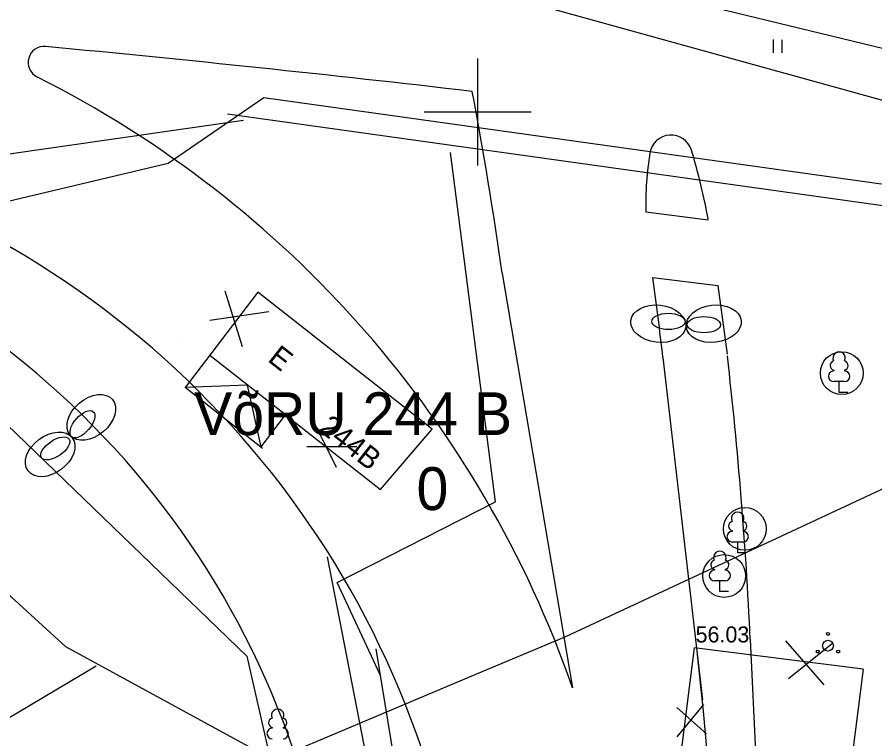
# Model space of a CAD drawing. Extents: x 9156 to 9809, y 2728 to 4000.
# Drawn here: x 9478.48 to 9518.57, y 3670.71 to 3704.43 of the extents above; entities that cross this region are included whole.
import ezdxf

# ---------------------------------------------------------------- set-up
doc = ezdxf.new("R2010")
doc.units = 0
for name, color, linetype in [('Level 12', 7, 'Continuous'), ('Level 15', 7, 'Continuous'), ('Level 17', 7, 'Continuous'), ('Level 18', 7, 'Continuous'), ('Level 21', 7, 'Continuous'), ('Level 5', 7, 'Continuous'), ('Level 54', 7, 'Continuous'), ('Level 56', 7, 'Continuous'), ('Level 7', 7, 'Continuous'), ('Level 8', 7, 'Continuous')]:
    doc.layers.add(name, color=color, linetype=linetype)

msp = doc.modelspace()

# ---------------------------------------------------------------- linework, layer by layer
at = {"layer": 'Level 12'}
for p, q in [((9488.307, 3699.92), (9534.248, 3693.484)), ((9459.613, 3695.388), (9489.062, 3699.618)), ((9500.841, 3681.791), (9498.727, 3698.107)), ((9493.441, 3678.014), (9500.841, 3681.791)), ((9495.459, 3673.67), (9493.441, 3678.014)), ((9498.274, 3656.637), (9495.253, 3674.917))]:
    msp.add_line(p, q, dxfattribs=at)
at = {"layer": 'Level 15'}
msp.add_lwpolyline([(9437.581, 3686.241), (9462.367, 3692.104), (9485.532, 3697.606), (9490, 3700.675), (9527.906, 3695.387)], dxfattribs=at)
at = {"layer": 'Level 17'}
msp.add_line((9496.063, 3663.383), (9492.991, 3679.211), dxfattribs=at)
msp.add_arc((9453.534, 3657.259), 40, 9.3105, 75.7638, dxfattribs=at)
at = {"layer": 'Level 18'}
for p, q in [((9507.867, 3695.337), (9510.78, 3694.968)), ((9501.153, 3692.453), (9504.44, 3673.096)), ((9508.194, 3692.272), (9511.23, 3691.887)), ((9511.23, 3691.887), (9511.666, 3688.685)), ((9508.665, 3688.523), (9510.518, 3672.533)), ((9512.748, 3675.359), (9513.212, 3665.616))]:
    msp.add_line(p, q, dxfattribs=at)
for centre, radius, start, end in [((9479.737, 3702.313), 0.75, 84.5765, 243.2936), ((9386.491, 2720.179), 987.3, 83.412623, 84.576467), ((9456.66, 3656.441), 50.6, 19.2175, 63.2936), ((9312.974, 3665.85), 190.05, 8.05166, 10.6463), ((9509.042, 3697.925), 1, 16.7546, 170.8283), ((9481.608, 3689.666), 29.65, 10.3017, 16.7546), ((9456.66, 3656.441), 43, 11.6855, 74.8696), ((9522.863, 3695.693), 15, 170.8283, 181.3602), ((9312.974, 3665.85), 197, 6.60881, 7.70773), ((9312.974, 3665.85), 200, 2.72499, 6.53209), ((9360.923, 3657.331), 150.35, 345.17244, 6.60878)]:
    msp.add_arc(centre, radius, start, end, dxfattribs=at)
at = {"layer": 'Level 21'}
for p, q in [((9488.177, 3691.646), (9489.001, 3689.036)), ((9487.49, 3690.273), (9490.236, 3690.685)), ((9486.209, 3689.434), (9486.209, 3689.434)), ((9492.296, 3685.601), (9493.394, 3683.403)), ((9492.021, 3684.365), (9494.355, 3684.365)), ((9514.399, 3675.297), (9516.184, 3673.236)), ((9516.596, 3675.16), (9514.536, 3673.511)), ((9510.555, 3672.316), (9509.319, 3670.804)), ((9509.319, 3672.178), (9510.692, 3670.942))]:
    msp.add_line(p, q, dxfattribs=at)
for centre in [(9517.021, 3687.799), (9512.491, 3680.518), (9511.53, 3678.319)]:
    msp.add_circle(centre, 1, dxfattribs=at)
at = {"layer": 'Level 54'}
for p, q in [((9525.323, 3698.769), (9500, 3705.781)), ((9509.597, 3705.253), (9524.201, 3701.7)), ((9513.819, 3703.38), (9513.819, 3702.76)), ((9514.224, 3703.369), (9514.224, 3702.76)), ((9500, 3702.5), (9500, 3697.5)), ((9500, 3702.5), (9500, 3697.5)), ((9500, 3702.5), (9500, 3697.5)), ((9500, 3702.5), (9500, 3697.5)), ((9500, 3702.5), (9500, 3697.5)), ((9500, 3702.5), (9500, 3697.5)), ((9500, 3702.5), (9500, 3697.5)), ((9497.5, 3700), (9502.5, 3700)), ((9497.5, 3700), (9500, 3700)), ((9497.5, 3700), (9500, 3700)), ((9497.5, 3700), (9500, 3700)), ((9500, 3700), (9502.5, 3700)), ((9500, 3700), (9502.5, 3700)), ((9500, 3700), (9502.5, 3700)), ((9516.649, 3687.932), (9516.649, 3687.9)), ((9517.149, 3687.932), (9517.149, 3687.9)), ((9517.149, 3687.4), (9516.649, 3687.4)), ((9516.899, 3686.9), (9516.899, 3687.4)), ((9517.299, 3686.9), (9516.899, 3686.9)), ((9491.013, 3685.849), (9491.013, 3685.849)), ((9491.013, 3685.848), (9491.013, 3685.848)), ((9497.879, 3685.175), (9497.879, 3685.175)), ((9504.119, 3675.494), (9524.201, 3684.845)), ((9489.875, 3684.353), (9489.875, 3684.353)), ((9495.454, 3682.356), (9495.454, 3682.356)), ((9511.907, 3680.437), (9511.907, 3680.405)), ((9512.407, 3680.437), (9512.407, 3680.405)), ((9512.407, 3679.905), (9511.907, 3679.905)), ((9512.157, 3679.405), (9512.157, 3679.905)), ((9512.557, 3679.405), (9512.157, 3679.405)), ((9511.073, 3678.623), (9511.073, 3678.591)), ((9511.573, 3678.623), (9511.573, 3678.591)), ((9511.573, 3678.091), (9511.073, 3678.091)), ((9511.323, 3677.591), (9511.323, 3678.091)), ((9511.723, 3677.591), (9511.323, 3677.591)), ((9504.119, 3675.494), (9504.119, 3675.494)), ((9480.751, 3675.008), (9480.751, 3675.008)), ((9510.126, 3674.962), (9510.126, 3674.962)), ((9518.027, 3673.959), (9510.126, 3674.962)), ((9482.174, 3674.124), (9482.174, 3674.124)), ((9490.404, 3671.242), (9490.404, 3671.21)), ((9490.904, 3671.242), (9490.904, 3671.21))]:
    msp.add_line(p, q, dxfattribs=at)
for points in [[(9489.728, 3691.587), (9486.333, 3687.124)], [(9497.879, 3685.175), (9489.728, 3691.586)], [(9491.013, 3685.848), (9487.477, 3688.629)], [(9489.469, 3670.261), (9480.751, 3675.008), (9468.298, 3686.386), (9465.685, 3688.526)], [(9489.875, 3684.353), (9489.245, 3687.238), (9486.333, 3687.124)], [(9489.946, 3684.282), (9486.333, 3687.124)], [(9489.875, 3684.353), (9491.013, 3685.848)], [(9491.013, 3685.849), (9495.454, 3682.356), (9497.879, 3685.175)], [(9500, 3673.76), (9504.119, 3675.494)], [(9510.126, 3674.962), (9508.48, 3661.998)], [(9476.571, 3670.806), (9482.174, 3674.124)], [(9490.691, 3669.842), (9500, 3673.76)], [(9518.027, 3673.959), (9514.804, 3648.572)]]:
    msp.add_lwpolyline(points, dxfattribs=at)
for centre, radius in [((9516.379, 3675.613), 0.0707), ((9516.379, 3675.063), 0.25), ((9515.903, 3674.788), 0.0707), ((9516.855, 3674.788), 0.0707)]:
    msp.add_circle(centre, radius, dxfattribs=at)
for centre, radius, start, end in [((9516.899, 3688.5), 0.292, 332.5799, 207.4201), ((9516.699, 3688.15), 0.224, 105.2441, 257.079), ((9517.099, 3688.15), 0.224, 282.921, 74.7559), ((9516.649, 3687.65), 0.25, 90, 270), ((9517.149, 3687.65), 0.25, 270, 90), ((9512.157, 3681.005), 0.292, 332.5799, 207.4201), ((9511.957, 3680.655), 0.224, 105.2441, 257.079), ((9512.357, 3680.655), 0.224, 282.921, 74.7559), ((9511.907, 3680.155), 0.25, 90, 270), ((9512.407, 3680.155), 0.25, 270, 90), ((9511.323, 3679.191), 0.292, 332.5799, 207.4201), ((9511.123, 3678.841), 0.224, 105.2441, 257.079), ((9511.523, 3678.841), 0.224, 282.921, 74.7559), ((9511.073, 3678.341), 0.25, 90, 270), ((9511.573, 3678.341), 0.25, 270, 90), ((9490.654, 3671.81), 0.292, 332.5799, 207.4201), ((9490.454, 3671.46), 0.224, 105.2441, 257.079), ((9490.854, 3671.46), 0.224, 282.921, 74.7559), ((9490.404, 3670.96), 0.25, 90, 270), ((9490.904, 3670.96), 0.25, 270, 90)]:
    msp.add_arc(centre, radius, start, end, dxfattribs=at)
msp.add_open_spline([(9456.036, 3699.596), (9459.877, 3701.043), (9462.13, 3701.966), (9465.816, 3703.444), (9468.745, 3704.598), (9470.032, 3705.126), (9471.191, 3705.455), (9484.079, 3707.958), (9487.812, 3708.551), (9490.419, 3708.749), (9495.812, 3709.078), (9498.129, 3709.078), (9499.964, 3708.913)], degree=2, dxfattribs=at)
at = {"layer": 'Level 56'}
for p, q in [((9507.867, 3695.337), (9510.78, 3694.968)), ((9501.153, 3692.453), (9504.44, 3673.096)), ((9508.194, 3692.272), (9511.23, 3691.887)), ((9511.23, 3691.887), (9511.666, 3688.685)), ((9508.665, 3688.523), (9510.518, 3672.533)), ((9496.063, 3663.383), (9492.991, 3679.211)), ((9512.748, 3675.359), (9513.212, 3665.616))]:
    msp.add_line(p, q, dxfattribs=at)
for centre, radius, start, end in [((9479.737, 3702.313), 0.75, 84.5765, 243.2936), ((9386.491, 2720.179), 987.3, 83.412623, 84.576467), ((9456.66, 3656.441), 50.6, 19.2175, 63.2936), ((9312.974, 3665.85), 190.05, 8.05166, 10.6463), ((9509.042, 3697.925), 1, 16.7546, 170.8283), ((9481.608, 3689.666), 29.65, 10.3017, 16.7546), ((9456.66, 3656.441), 43, 11.6855, 74.8696), ((9522.863, 3695.693), 15, 170.8283, 181.3602), ((9453.534, 3657.259), 40, 9.3105, 75.7638), ((9312.974, 3665.85), 197, 6.60881, 7.70773), ((9312.974, 3665.85), 200, 2.72499, 6.53209), ((9360.923, 3657.331), 150.35, 345.17244, 6.60878)]:
    msp.add_arc(centre, radius, start, end, dxfattribs=at)
at = {"layer": 'Level 7'}
for p, q in [((9474.788, 3688.481), (9489.206, 3674.567)), ((9489.206, 3674.567), (9493.16, 3657.324))]:
    msp.add_line(p, q, dxfattribs=at)
at = {"layer": 'Level 8'}
for centre, major_axis, ratio in [((9508.447, 3690.106), (1.285, -0.15), 0.674652), ((9508.447, 3690.106), (1.285, -0.15), 0.674652), ((9508.447, 3690.106), (1.285, -0.15), 0.674652), ((9508.447, 3690.106), (1.285, -0.15), 0.674652), ((9511.039, 3690.106), (-1.285, -0.15), 0.674652), ((9511.039, 3690.106), (-1.285, -0.15), 0.674652), ((9511.039, 3690.106), (-1.285, -0.15), 0.674652), ((9511.039, 3690.106), (-1.285, -0.15), 0.674652), ((9508.918, 3690.213), (-0.778, 0.002), 0.486914), ((9508.918, 3690.213), (-0.778, 0.002), 0.486914), ((9508.918, 3690.213), (-0.778, 0.002), 0.486914), ((9508.918, 3690.213), (-0.778, 0.002), 0.486914), ((9510.58, 3690.062), (-0.778, 0.002), 0.486914), ((9510.58, 3690.062), (-0.778, 0.002), 0.486914), ((9510.58, 3690.062), (-0.778, 0.002), 0.486914), ((9510.58, 3690.062), (-0.778, 0.002), 0.486914), ((9481.942, 3685.73), (-0.986, -0.837), 0.674652), ((9481.942, 3685.73), (-0.986, -0.837), 0.674652), ((9481.942, 3685.73), (-0.986, -0.837), 0.674652), ((9481.942, 3685.73), (-0.986, -0.837), 0.674652), ((9481.53, 3685.408), (-0.507, -0.589), 0.486914), ((9481.53, 3685.408), (-0.507, -0.589), 0.486914), ((9481.53, 3685.408), (-0.507, -0.589), 0.486914), ((9481.53, 3685.408), (-0.507, -0.589), 0.486914), ((9480.018, 3684.001), (1.034, 0.776), 0.674652), ((9480.018, 3684.001), (1.034, 0.776), 0.674652), ((9480.018, 3684.001), (1.034, 0.776), 0.674652), ((9480.018, 3684.001), (1.034, 0.776), 0.674652), ((9480.258, 3684.279), (0.646, 0.434), 0.486914), ((9480.258, 3684.279), (0.646, 0.434), 0.486914), ((9480.258, 3684.279), (0.646, 0.434), 0.486914), ((9480.258, 3684.279), (0.646, 0.434), 0.486914)]:
    msp.add_ellipse(centre, major_axis=major_axis, ratio=ratio, dxfattribs=at)

# ---------------------------------------------------------------- texts
at = {"layer": 'Level 5'}
for s, p in [('VõRU 244 B', (9486.746, 3684.901)), ('0', (9497.145, 3681.401))]:
    msp.add_text(s, height=2, dxfattribs=at).set_placement(p)
at = {"layer": 'Level 54'}
for s, p in [('E', (9490.141, 3688.385)), ('244B', (9492.523, 3685.133))]:
    msp.add_text(s, height=1, rotation=321.8137, dxfattribs=at).set_placement(p)
msp.add_text('56.03', height=0.75, dxfattribs=at).set_placement((9510.19, 3675.213))

doc.saveas('drawing.dxf')
